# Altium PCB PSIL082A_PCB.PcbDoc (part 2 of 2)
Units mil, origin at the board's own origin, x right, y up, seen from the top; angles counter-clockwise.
Board outline 3500 x 2700 mil, 4 copper layers (Top Layer, Signal Layer 1, Signal Layer 2, Bottom Layer), stack 61.2 mil thick; 62 components, 57 nets, 283 pads, 94 vias.
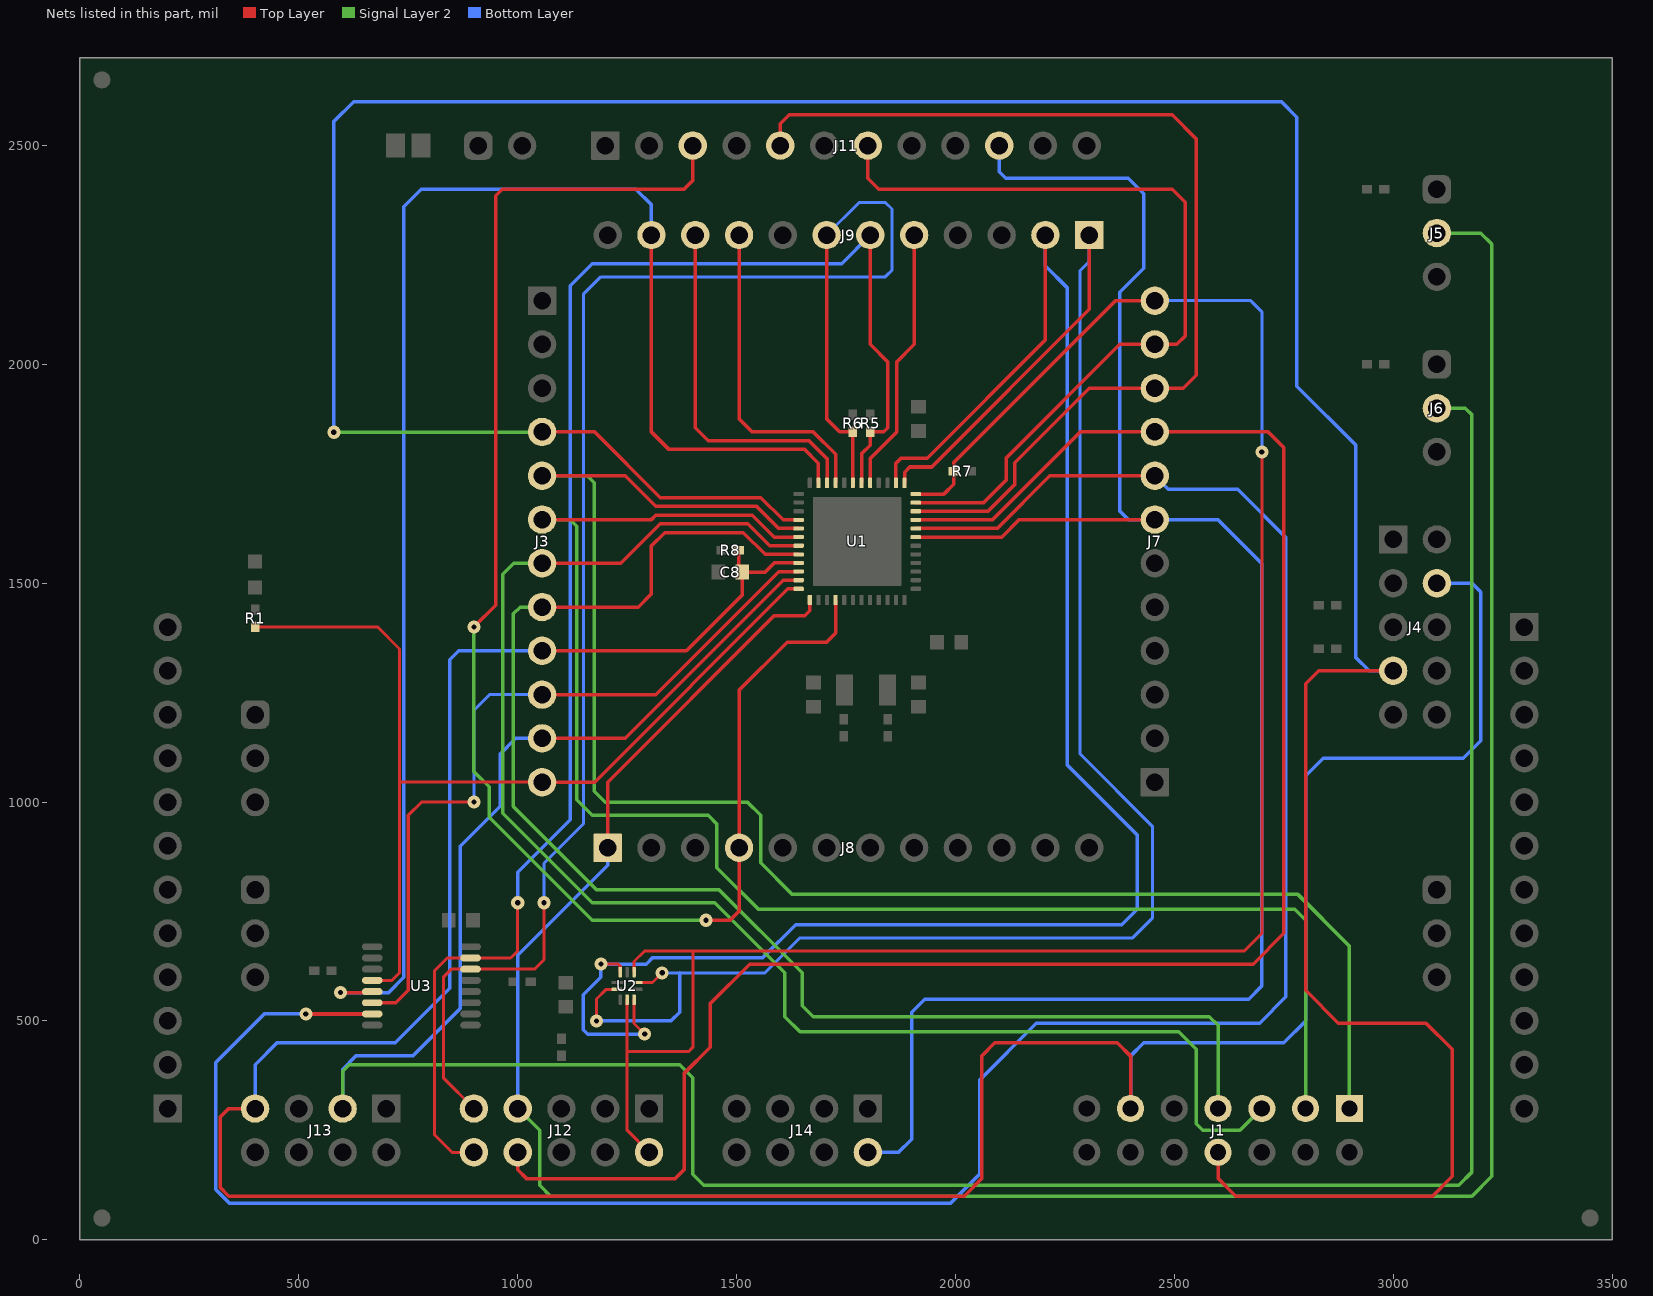
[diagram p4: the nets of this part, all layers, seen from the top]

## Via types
v1: diameter 30, hole 12, Top Layer to Bottom Layer, 73 vias
v2: diameter 19.68, hole 7.87, Top Layer to Bottom Layer, 21 vias

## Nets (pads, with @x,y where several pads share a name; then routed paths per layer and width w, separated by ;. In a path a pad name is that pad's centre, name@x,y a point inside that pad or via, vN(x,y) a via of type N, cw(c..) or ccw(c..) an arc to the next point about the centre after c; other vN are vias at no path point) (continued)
"P1.6 PG2": J7.7 J11.10 J14.2 U1.19 | length 4288.3
  Top Layer w8: U1.19@1909.45,1605.43 2105.43,1605.43 2145.59,1645.59 J7.7@2455.59,1645.59
  Bottom Layer w8: J14.2@1800,200 1870,200 1900,230 1900,520 1930,550 2670,550 2700,580 2700,1545 2599.41,1645.59 J7.7@2455.59,1645.59 2394.41,1645.59 2375,1665 2375,2165.01 2430,2220.01 2430,2390 2395,2425 2115,2425 2100,2440 J11.10@2100,2500
"P1.7 DIS PORTS": J7.8 U1.20 U3.7 | length 5476.9
  Top Layer w8: U1.20@1909.45,1625.12 2095.12,1625.12 2215.59,1745.59 J7.8@2455.59,1745.59
  Top Layer w10: v1(516.02,516.02) U3.7@667.8,516.02
  Bottom Layer w8: v1(516.02,516.02) 421.02,516.02 310,405 310,115 341.87,83.13 1988.13,83.13 2055,150 2055,365 2185,495 2695,495 2755,555 2755,1604.65 2644.65,1715 2486.18,1715 J7.8@2455.59,1745.59
"P2.7 SPI CLK USCI_A0": J7.9 J12.8 U1.21 | length 4266.2
  Top Layer w8: J12.8@1000,200 1000,160 1020,140 1360,140 1380,160 1380,380 1440,440 1440,540 1530,630 2680,630 2750,700 2750,1810 2714.41,1845.59 2285.59,1845.59 2084.8,1644.8 U1.21@1909.45,1644.8
"P3.0 I2C SDA USCI_B0": J7.10 J11.5 U1.22 | length 2369.5
  Top Layer w8: J11.5@1600,2500 1600,2550 1620,2570 2495,2570 2550,2515 2550,1975 2520.59,1945.59 2305.59,1945.59 2135.59,1775.59 2135.59,1725.59 2074.49,1664.49 U1.22@1909.45,1664.49
"P3.1 I2C SCL USCI_B0": J7.11 J11.7 U1.23 | length 1930.4
  Top Layer w8: J11.7@1800,2500 1800,2425 1825,2400 2495,2400 2525,2370 2525,2065 2505.59,2045.59 2375.59,2045.59 2115.59,1785.59 2115.59,1735.59 2064.17,1684.17 U1.23@1909.45,1684.17
"P3.2 SPI SLAVE TX EN USCI_A0": J7.12 J12.2 R7.1 U1.24 U2.4 U2.8 | length 4661.9
  Top Layer w7: U2.4@1250,548.5 1250,430 ; U2.8@1265.75,611.5 1265.75,635.75 1290,660 1400,660 ; J12.2@1300,200 1250,250 1250,430 ; v1(2700,1800) 2700,700 2660,660 1400,660 ; 1250,430 1390,430 1400,440 1400,660
  Top Layer w8: U1.24@1909.45,1703.86 1973.86,1703.86 1995.91,1725.91 1995.91,1775.91 2365.59,2145.59 J7.12@2455.59,2145.59
  Bottom Layer w7: J7.12@2455.59,2145.59 2674.41,2145.59 2700,2120 v1(2700,1800)
"P3.3 UART TX USCI_A0/SPI SIMO": J9.1 U1.25 U2.2 U2.7 | length 4038.4
  Top Layer w7: v1(1180,500) 1180,550 1202.13,572.13 U2.2@1226.38,572.13 ; U2.7@1273.62,587.87 1307.87,587.87 v1(1330,610)
  Top Layer w8: U1.25@1883.86,1729.45 1883.86,1753.86 1895.59,1765.59 1945.59,1765.59 2305.59,2125.59 J9.1@2305.59,2295.59
  Bottom Layer w7: v1(1330,610) 1565,610 1645,690 2405,690 2450,735 2450,945 2285,1110 2285,2214.41 2305.59,2235 J9.1@2305.59,2295.59
  Bottom Layer w8: v1(1180,500) 1350,500 1370,520 1370,609.65
"P3.4 UART RX USCI_A0/SPI SOMI": J9.2 U1.26 U2.5 U2.10 | length 4106.3
  Top Layer w7: v1(1190,630) 1230,630 1234.25,625.75 U2.10@1234.25,611.5 ; U2.5@1265.75,548.5 1265.75,494.25 v1(1290,470)
  Top Layer w8: U1.26@1864.17,1729.45 1864.17,1774.17 1875.59,1785.59 1935.59,1785.59 2205.59,2055.59 J9.2@2205.59,2295.59
  Bottom Layer w8: v1(1290,470) 1160,470 1150,480 1150,560 1190,600 v1(1190,630) 1293.84,630 1308.84,645 1560,645 1635,720 2380,720 2415,755 2415,925 2255,1085 2255,2175.59 2205.59,2225 J9.2@2205.59,2295.59
"P4.0 SPI CLK USCI_A1": J9.5 U1.29 | length 607.8
  Top Layer w8: U1.29@1805.12,1729.45 1805.12,1785.12 1865.59,1845.59 1865.59,2005.59 1905.59,2045.59 J9.5@1905.59,2295.59
"P4.1 I2C SDA USCI_B1": J9.6 J12.10 R5.1 U1.30 U3.15 | length 3618.8
  Top Layer w7: J12.10@900,200 850,200 810,240 810,615 838.98,643.98 U3.15@892.2,643.98 983.98,643.98 1000,660 v1(1000,770)
  Top Layer w8: U1.30@1785.43,1729.45 1785.43,1795.43 1805.59,1815.59 R5.1@1805.59,1845.91 1835.91,1845.91 1845.59,1855.59 1845.59,2005.59 1805.59,2045.59 J9.6@1805.59,2295.59
  Bottom Layer w8: v1(1000,770) 1000,840 1120,960 1120,2180 1170,2230 1740,2230 J9.6@1805.59,2295.59
"P4.2 I2C SCL USCI_B1": J9.7 J12.9 R6.1 U1.31 U3.14 | length 3795.7
  Top Layer w7: J12.9@900,300 830,370 830,600 848.39,618.39 U3.14@892.2,618.39 1038.39,618.39 1060,640 v1(1060,770)
  Top Layer w8: J9.7@1705.59,2295.59 1705.59,1875.59 1735.28,1845.91 R6.1@1765.59,1845.91 ; U1.31@1765.75,1729.45 R6.1@1765.75,1845.75
  Bottom Layer w7: v1(1060,770) 1060,860 1150,950 1150,2160 1190,2200 1840,2200 1855,2215 1855,2355 1840,2370 1780,2370 J9.7@1705.59,2295.59
"P4.4 SPI SIMO/UART TX USCI_A1": J9.9 U1.33 | length 739.6
  Top Layer w8: J9.9@1505.59,2295.59 1505.59,1875.59 1535.59,1845.59 1675.59,1845.59 1726.38,1794.8 U1.33@1726.38,1729.45
"P4.5 SPI SOMI/UART RX USCI_A1": J9.10 U1.34 | length 825.6
  Top Layer w8: J9.10@1405.59,2295.59 1405.59,1855.59 1435.59,1825.59 1665.59,1825.59 1706.69,1784.49 U1.34@1706.69,1729.45
"P4.6 RESERVED": J9.11 U1.35 U3.5 | length 3564.6
  Top Layer w8: v1(595,565) 665.59,565 U3.5@667.8,567.2 ; J9.11@1305.59,2295.59 1305.59,1845.59 1345.59,1805.59 1655.59,1805.59 1687.01,1774.17 U1.35@1687.01,1729.45
  Bottom Layer w8: v1(595,565) 705,565 740,600 740,2360 780,2400 1270,2400 1305.59,2364.41 J9.11@1305.59,2295.59
"P5.0 RESET": J8.4 J11.3 U1.4 | length 3531.5
  Top Layer w8: v1(900,1400) 950,1450 950,2385 965,2400 1380,2400 1400,2420 J11.3@1400,2500 ; v1(1430,730) 1485,730 1505.59,750.59 J8.4@1505.59,895.59 1505.59,1255.59 1615.59,1365.59 1705.59,1365.59 1726.38,1386.38 U1.4@1726.38,1461.73
  Signal Layer 2 w8: v1(900,1400) 900,1070 935,1035 935,965 1170,730 v1(1430,730)
"P6.0 INT to host": J3.10 U1.46 U3.6 | length 1739.3
  Top Layer w7: U3.6@667.8,541.61 721.61,541.61 750,570 750,970 780,1000 v1(900,1000)
  Top Layer w8: J3.10@1055.59,1245.59 1315.59,1245.59 1596.69,1526.69 U1.46@1641.73,1526.69
  Bottom Layer w7: v1(900,1000) 900,1210 935.59,1245.59 J3.10@1055.59,1245.59
"P6.1 I2C or UART/SPI": J3.11 J6.2 J13.3 U1.47 | length 6624.1
  Top Layer w8: J3.11@1055.59,1145.59 1245.59,1145.59 1607.01,1507.01 U1.47@1641.73,1507.01
  Signal Layer 2 w8: J13.3@600,300 600,385 615,400 1370,400 1400,370 1400,150 1425,125 3150,125 3180,155 3180,1885 3165,1900 J6.2@3100,1900
  Bottom Layer w8: J13.3@600,300 600,390 630,420 760,420 868.58,528.58 868.58,899.29 960,990.71 960,1110 995.59,1145.59 J3.11@1055.59,1145.59
"P6.2 GUARDBAND": J3.12 R1.1 U1.48 U3.4 | length 2254.9
  Top Layer w7: R1.1@400,1400.32 679.68,1400.32 730,1350 730,1045.59 ; U3.4@667.8,592.8 712.8,592.8 730,610 730,1045.59 ; J3.12@1055.59,1045.59 730,1045.59
  Top Layer w8: J3.12@1055.59,1045.59 1175.59,1045.59 1617.32,1487.32 U1.48@1641.73,1487.32
"P6.3 BSL SEL": J5.2 J8.1 J12.7 U1.1 | length 6144.2
  Top Layer w8: J8.1@1205.59,895.59 1205.59,1045.59 1585.59,1425.59 1655.59,1425.59 1667.32,1437.32 U1.1@1667.32,1461.73
  Signal Layer 2 w8: J12.7@1000,300 1050,250 1050,125 1075,100 3180,100 3225,145 3225,2275 3200,2300 J5.2@3100,2300
  Bottom Layer w8: J12.7@1000,300 1000,650 1205.59,855.59 J8.1@1205.59,895.59
RSTDVCC/SBWTDIO: C8.1 J1.11 J3.9 J4.4 J13.7 R8.2 U1.45 | length 7112.4
  Top Layer w8: J13.7@400,300 340,300 320,280 320,120 340,100 2020,100 2060,140 2060,420 2090,450 2370,450 2400,420 J1.11@2400,300 ; J3.9@1055.59,1345.59 1385.59,1345.59 1513.15,1473.15 C8.1@1513.15,1525.59 ; R8.2@1505.28,1575.59 1505.28,1533.46 C8.1@1513.15,1525.59 ; U1.45@1641.73,1546.38 1586.38,1546.38 1565.59,1525.59 C8.1@1513.15,1525.59
  Bottom Layer w8: J13.7@400,300 400,400 450,450 720,450 845,575 845,1325 865.59,1345.59 J3.9@1055.59,1345.59 ; J1.11@2400,300 2400,420 2430,450 2750,450 2800,500 2800,1060 2840,1100 3160,1100 3200,1140 3200,1480 3180,1500 J4.4@3100,1500
TCK: J1.7 J3.8 U1.44 | length 3304.6
  Top Layer w8: J3.8@1055.59,1445.59 1275.59,1445.59 1305.59,1475.59 1305.59,1585.59 1335.59,1615.59 1515.59,1615.59 1565.12,1566.06 U1.44@1641.73,1566.06
  Signal Layer 2 w8: J3.8@1055.59,1445.59 1005.59,1445.59 990,1430 990,990 1180,800 1460,800 1650,610 1650,535 1675,510 2580,510 2600,490 J1.7@2600,300
TDI/TCLK: J1.3 J3.6 U1.42 | length 3589.4
  Top Layer w8: J3.6@1055.59,1645.59 1305.59,1645.59 1315.59,1655.59 1535.59,1655.59 1585.75,1605.43 U1.42@1641.73,1605.43
  Signal Layer 2 w8: J3.6@1055.59,1645.59 1119.41,1645.59 1135,1630 1135,1005 1170,970 1435,970 1455,950 1455,850 1550,755 2775,755 2800,730 J1.3@2800,300
TDO: J1.1 J3.5 U1.41 | length 3773.4
  Top Layer w8: J3.5@1055.59,1745.59 1245.59,1745.59 1315.59,1675.59 1545.59,1675.59 1596.06,1625.12 U1.41@1641.73,1625.12
  Signal Layer 2 w8: J3.5@1055.59,1745.59 1159.41,1745.59 1175,1730 1175,1025 1200,1000 1525,1000 1555,970 1555,861.37 1626.37,790 2781.37,790 2900,671.37 J1.1@2900,300
TEST/SBWTCK: J1.8 J3.4 J4.7 U1.40 | length 7699.3
  Top Layer w8: J3.4@1055.59,1845.59 1175.59,1845.59 1325.59,1695.59 1555.59,1695.59 1606.38,1644.8 U1.40@1641.73,1644.8 ; J1.8@2600,200 2600,140 2640,100 3090,100 3135,145 3135,435 3075,495 2875,495 2800,570 2800,1270 2830,1300 J4.7@3000,1300
  Signal Layer 2 w8: v1(580,1845) J3.4@1055,1845
  Bottom Layer w8: v1(580,1845) 580,2555 625,2600 2745,2600 2780,2565 2780,1950 2915,1815 2915,1330 2945,1300 J4.7@3000,1300
TMS: J1.5 J3.7 U1.43 | length 3503.9
  Top Layer w8: J3.7@1055.59,1545.59 1235.59,1545.59 1325.59,1635.59 1525.59,1635.59 1575.43,1585.75 U1.43@1641.73,1585.75
  Signal Layer 2 w8: J3.7@1055.59,1545.59 990.59,1545.59 965.59,1520.59 965.59,974.41 1170,770 1450,770 1610,610 1610,510 1645,475 2510,475 2550,435 2550,265 2565,250 2650,250 J1.5@2700,300
pads on no net: FID1.1 FID2.1 FID3.1 J1.6 J1.10 J1.12 J1.13 J1.14 J3.2 J3.3 J4.2 J4.9 J4.10 J8.7 J8.8 J8.12 J11.11 J13.1 J13.2 J13.5 J13.6 J14.1 J14.3 J14.4 J14.5 J14.6 J14.7 J14.8 J17.2 J17.3 J17.4 J17.5 J17.7 J17.8 J17.9 J17.10 J17.11 J18.2 J18.3 J18.4 J18.5 J18.7 J18.8 J18.9 J18.10 J18.11 LBL1.0 SH-J1.0 SH-J2.0 SH-J3.0 SH-J4.0 SH-J5.0 U1.38 U1.39 U3.9 U3.10 U3.11 U3.12

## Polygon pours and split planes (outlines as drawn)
GND_ISO on Signal Layer 1 "SIGNAL_LAYER_1_GND_ISO_P000" (solid, remove dead copper, pour order 0): 50,2650 3450,2650 3450,50 50,50
DVCC on Signal Layer 2 "SIGNAL_LAYER_2_DVCC_P002" (solid, remove dead copper, pour order 2): 50,2650 50,50 3450,50 3450,2650
GND_ISO on Top Layer "TOP_LAYER_GND_ISO_P004" (solid, remove dead copper, pour order 4): 50,2650 3450,2650 3450,50 50,50
GND_ISO on Bottom Layer "BOTTOM_LAYER_GND_ISO_P006" (solid, remove dead copper, pour order 6): 3450,2650 3450,50 50,50 50,2650

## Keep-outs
Keep-Out Layer:
  lines w10: -5,0 ccw(c0,0) 0,-5 ; -5,0 ccw(c0,0) 0,-5 ; -5,0 -5,2700 ; -5,2700 cw(c0,2700) 0,2705 ; -5,2700 cw(c0,2700) 0,2705 ; 0,-5 3500,-5 ; 0,2705 3500,2705 ; 3500,-5 ccw(c3500,0) 3505,0 ; 3500,-5 ccw(c3500,0) 3505,0 ; 3500,2705 cw(c3500,2700) 3505,2700 ; 3500,2705 cw(c3500,2700) 3505,2700 ; 3505,0 3505,2700
  text ".Layer_Name" at 577,-858.49 h60

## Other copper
Top Layer:
  text ".Layer_Name" at 567,-858.49 h60
Signal Layer 1:
  text ".Layer_Name" at 577,-858.49 h60
Signal Layer 2:
  text ".Layer_Name" at 572,-863.49 h60
Bottom Layer:
  text ".Layer_Name" at 577,-858.49 h60

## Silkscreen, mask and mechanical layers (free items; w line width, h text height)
Top Overlay:
  lines w8: 1045,350 1045,390 1150,390 1150,350
  text "DVCC/3.3V_ISO" at 735,2585 h72.83
  text "'.PRJ_Number'.PCB_Rev" at 160,2460 h108.27
  text "HIGH" at 3190,2380 h72.83
  text "PIN 25" at 2290,2365 h70
  text "PIN 36" at 1035,2360 h70
  text "Reserved" at 3187.88,2270.75 h72.83
  text "LOW" at 3190,2170 h72.83
  text "PIN 37" at 780,2125 h70
  text "PIN 24" at 2535,2120 h70
  text "I2C" at 3170,1985 h72.83
  text "UART/SPI" at 3165,1775 h72.83
  text "BSL" at 3195,1490 h72.83
  text "PIN 48" at 795,1030 h70
  text "PIN 13" at 2535,1015 h70
  text "PIN 1" at 1085,785 h70
  text "INT" at 2829.25,784.63 h72.83
  text "PIN 12" at 2300,775 h70
  text "DVCC" at 2829.25,684.99 h72.83
  text "EXT" at 2829.25,582.12 h72.83
  text "JTAG" at 2510,460 h72.83
  text "(29)" at 315,390 h72.83
  text "(1)" at 1770,390 h72.83
  text "9" at 850,360 h72.83
  text "1" at 1330.53,357.71 h72.83
  text "2" at 1315,95 h72.83
  text "10" at 845,90 h72.83
  text "USB2ANY" at 950,80 h72.83
  text "(2)" at 1770,70 h72.83
  text "(30)" at 310,60 h72.83
  text ".Layer_Name" at 577,-858.49 h60
Bottom Overlay:
  text ".Layer_Name" at 577,-858.49 h60
Top Paste:
  text ".Layer_Name" at 577,-858.49 h60
Bottom Paste:
  text ".Layer_Name" at 577,-858.49 h60
Top Solder:
  text ".Layer_Name" at 577,-858.49 h60
  text ".Layer_Name" at 577,-858.49 h60
Bottom Solder:
  text ".Layer_Name" at 577,-858.49 h60
Drill Guide:
  text ".Layer_Name" at 577,-858.49 h60
M1 Board Outline:
  the board outline again, w10
  text ".Layer_Name" at 577,-858.49 h60
M2 Board Dimensions:
  rectangle: 125,-400 500,-275
  rectangle: 0,-275 125,-150
  lines w7: 0,-275 1000,-275 ; 125,-400 125,-150 ; 250,-400 250,-150 ; 500,-400 500,-150 ; 750,-400 750,-150 ; 0,-400 0,-150 1000,-150 1000,-400 0,-400
  text ".Layer_Name" at 577,-858.49 h60
M3 3D STEP Top:
  text ".Layer_Name" at 577,-858.49 h60
M4 3D STEP Bottom:
  text ".Layer_Name" at 577,-858.49 h60
M5 Assembly Top:
  lines w10: -292,-930.17 6308,-930.17 ; -292,-726.83 6310,-726.83 ; -292,-523.5 -292,-1133.5 3713,-1133.5 6310,-1133.5 6310,-523.5 -291.5,-523.5 -291.5,-1133.5 1284,-1133.5 ; 2173,-1133.5 2173,-523.5 ; 3440,-726.83 3440,-523.5 ; 4280,-726.83 4280,-523.5 ; 4902,-1140 4902,-937.17
  text "COMPONENTS MARKED 'DNP' SHOULD NOT BE POPULATED." at 1153.5,-318.5 h60
  text "ASSEMBLY VARIANT:" at 1153,-434 h60
  text ".VariantName" at 2189,-434 h60
  text "PCB VIEWED FROM TOP SIDE" at -228.5,-655.67 h60
  text "BOARD #:" at 2248,-655.67 h60
  text ".PRJ_Number" at 2793.5,-655.67 h60
  text "REV:" at 3638,-655.67 h60
  text ".PCB_Rev" at 3929.5,-655.67 h60
  text "SVN REV:" at 4476,-655.67 h60
  text ".VersionControl_RevNumber" at 4982,-655.67 h60
  text "TID #:" at 2248,-859 h60
  text ".TID" at 2793.5,-859 h60
  text "PLOT NAME =" at -228.5,-1064.34 h60
  text ".plot_File_Name" at 577,-1064.34 h60
  text "GENERATED    :" at 2250,-1064.34 h60
  text ".Print_Date" at 3119.5,-1064.34 h60
  text ".Print_Time" at 3848.5,-1064.34 h60
  text "TEXAS INSTRUMENTS" at 5113,-1064.34 h60
M6 Assembly Bottom:
  lines w10: -292.5,-727.33 6309.5,-727.33 ; -290.5,-930.67 6309.5,-930.67 ; 1115.5,-1140.5 1115.5,-937.67 ; 1737.5,-727.33 1737.5,-524 ; 2577.5,-727.33 2577.5,-524 ; 3844.5,-1134 3844.5,-524 ; 4733.5,-1134 6309,-1134 6309,-524 -292.5,-524 -292.5,-1134 2304.5,-1134 6309.5,-1134 6309.5,-524
  text "COMPONENTS MARKED 'DNP' SHOULD NOT BE POPULATED." at 6102,-318 h60
  text ".VariantName" at 5058,-434 h60
  text "ASSEMBLY VARIANT:" at 6097,-434 h60
  text ".VersionControl_RevNumber" at 1035.5,-656.17 h60
  text "SVN REV:" at 1541.5,-656.17 h60
  text ".PCB_Rev" at 2088,-656.17 h60
  text "REV:" at 2379.5,-656.17 h60
  text ".PRJ_Number" at 3224,-656.17 h60
  text "BOARD #:" at 3769.5,-656.17 h60
  text "PCB VIEWED FROM BOTTOM SIDE" at 6246,-656.17 h60
  text ".TID" at 3224,-859.5 h60
  text "TID #:" at 3769.5,-859.5 h60
  text "TEXAS INSTRUMENTS" at 904.5,-1064.84 h60
  text ".Print_Time" at 2169,-1064.84 h60
  text ".Print_Date" at 2898,-1064.84 h60
  text "GENERATED    :" at 3767.5,-1064.84 h60
  text ".plot_File_Name" at 5440.5,-1064.84 h60
  text "PLOT NAME =" at 6246,-1064.84 h60
M9 Title Sheet:
  drawing of 57 lines, arcs and shapes, not listed
  text "1" at 739.84,8036.5 h70
  text "2" at 3235.5,8036.5 h70
  text "3" at 5724.84,8036.5 h70
  text "4" at 8231.51,8036.5 h70
  text "5" at 10730.5,8036.5 h70
  text "6" at 13235.5,8036.5 h70
  text "A" at -416.5,6893.5 h70
  text "A" at 14383.5,6893.5 h70
  text "B" at -416.5,4513.5 h70
  text "B" at 14383.5,4513.5 h70
  text "C" at -416.5,2138.5 h70
  text "C" at 14383.5,2138.5 h70
  text "PROJECT TITLE:" at 11343.5,277.5 h45
  text ".PRJ_Title" at 11393.5,144.17 h70
  text "DESIGNED FOR:" at 11343.5,-23.5 h45
  text ".PRJ_Customer" at 11393.5,-163.5 h70
  text "D" at -416.5,-231.5 h70
  text "D" at 14383.5,-231.5 h70
  text "FILE NAME:" at 11343.5,-323.5 h45
  text ".PCB_File_Name_No_Path" at 11393.5,-443.5 h70
  text "Texas Instruments (TI) and/or its licensors do not warrant the accuracy or completeness of this specification" at 6374,-605.34 h45
  text "ENGINEER:" at 11343.5,-613.5 h45
  text "LAYOUT BY:" at 12848.5,-613.5 h45
  text "or any information contained therein. TI and/or its licensors do not warrant that this design will meet" at 6329.01,-718 h45
  text ".PRJ_Engineer" at 11393.5,-768.49 h70
  text ".PCB_Layout" at 12899,-768.49 h70
  text "the specifications, will be suitable for your application or fit for any particular purpose, or will operate in" at 6329.01,-830.67 h45
  text ".Layer_Name" at 577,-858.49 h60
  text "ALTIUM DESIGNER VERSION:" at 12848.5,-923.5 h45
  text "an implementation. TI and/or its licensors do not warrant that the design is production worthy. You should" at 6329.01,-943.33 h45
  text "completely validate and test your design implementation to confirm the system functionality for your application." at 6374,-1056 h45
  text ".print_Scale" at 11393.5,-1056.83 h70
  text ".Application_BuildNumber" at 12899,-1056.83 h70
  text "1" at 739.84,-1263.5 h70
  text "2" at 3235.5,-1263.5 h70
  text "3" at 5724.84,-1263.5 h70
  text "4" at 8231.51,-1263.5 h70
  text "5" at 10730.5,-1263.5 h70
  text "6" at 13235.5,-1263.5 h70
M10 Fab Notes:
  drawing of 189 lines, arcs and shapes, not listed
  text "DESIGN INFORMATION" at 12382.02,6356.17 h60
  text "MIN. TRACK WIDTH:" at 11737.46,6224.05 h60
  text "7" at 12833.7,6224.05 h60
  text "MIL" at 12988.46,6224.05 h60
  text "MIN. CLEARANCE:" at 11737.46,6099.92 h60
  text "0.2" at 12773.7,6099.93 h60
  text "mm" at 12988.46,6099.92 h60
  text "MIN. VIA PAD SIZE:" at 11737.46,5975.8 h60
  text "24" at 12803.71,5975.8 h60
  text "MIL" at 12988.46,5975.8 h60
  text "0.05mm (2MIL)" at 12432.46,5845.9 h60
  text "MINIMUM ANNULAR RING" at 11408.23,5837.67 h60
  text "EXTERNAL" at 13140.46,5837.67 h60
  text "PER" at 11608.23,5727.55 h60
  text "IPC-D-275 CLASS 2 LEVEL C" at 11828.23,5727.54 h60
  text "MIL, HOLES" at 13316.46,5627.07 h60
  text "+/-" at 12924,5618.48 h60
  text "+/-" at 13778,5618.48 h60
  text "REGISTRATION TOLERANCES:" at 11408.23,5617.42 h60
  text "METAL" at 12608,5617.42 h60
  text "5" at 13184.2,5617.42 h60
  text "3" at 14017.2,5617.42 h60
  text "MIL" at 14133.46,5617.42 h60
  text "HOLE SIZE TOLERANCE (UNLESS OTHERWISE SPECIFIED):" at 11408.23,5519.1 h60
  text "+/-" at 13778,5516.23 h60
  text "3" at 14017.2,5515.17 h60
  text "MIL" at 14133.46,5515.17 h60
  text "MATERIAL:" at 11333.46,5377.52 h60
  text "FR-4 High Tg" at 12319.9,5249 h60
  text "X" at 12175.46,5241.01 h60
  text "FR-408" at 11754.46,5236.49 h60
  text "OTHER" at 13242.46,5236.49 h60
  text "62 MIL (1.6mm) +/-10%" at 12074.56,5093.46 h60
  text "X" at 11954.46,5091.01 h60
  text "THICKNESS:" at 11408.23,5085.24 h60
  text "OTHER" at 13359.46,5085.24 h60
  text "TOLERANCE:" at 11408.23,4946.92 h60
  text "X" at 12256.46,4946.92 h60
  text "ANSI IPC-6012 TYPE 3 CLASS 2" at 12434.48,4946.92 h60
  text "OTHER +/-" at 12434.46,4802.73 h60
  text "BOW & TWIST:" at 11408.23,4657.54 h60
  text "X" at 12256.46,4657.54 h60
  text "ANSI IPC-6012 TYPE 3 CLASS 2" at 12434.48,4657.54 h60
  text "OTHER +/-" at 12434.46,4510.85 h60
  text "DRILLING:" at 11333.46,4380.23 h60
  text "NC_DRILL FILES" at 13094.46,4275.04 h60
  text "REFERENCE:" at 11408.23,4271.1 h60
  text "X" at 12065.46,4271.01 h60
  text "AS SHOWN" at 12243.46,4271.1 h60
  text "X" at 12966.46,4271.1 h60
  text "OTHER" at 13392.46,4128.85 h60
  text "PTH COPPER THICKNESS:" at 11407.91,4125.32 h60
  text "X" at 12547.14,4125.32 h60
  text "20-30 um" at 12675.14,4125.32 h60
  text "BOARD FINISH:" at 11333.46,3977.73 h60
  text "SILKSCREEN:" at 11488.68,3867.6 h60
  text "X" at 12446.46,3867.6 h60
  text "TOP" at 12563.46,3867.6 h60
  text "X" at 12956.46,3867.6 h60
  text "BOTTOM" at 13074.46,3867.6 h60
  text "SILKSCREEN COLOR:" at 11488.68,3712.41 h60
  text "X" at 12445.46,3712.41 h60
  text "WHITE" at 12563.46,3712.41 h60
  text "OTHER" at 13074.46,3712.41 h60
  text "X" at 12576.46,3568.96 h60
  text "GREEN" at 12694.46,3568.96 h60
  text "OTHER" at 13312.46,3568.96 h60
  text "SOLDER RESIST COLOR:" at 11488.68,3562.1 h60
  text "X" at 12576.46,3414.71 h60
  text "MATTE" at 12694.46,3414.71 h60
  text "SEMI-GLOSS" at 13312,3414.07 h60
  text "IMMERSION GOLD (ENIG)" at 12394.46,3241.94 h60
  text "ENEPIG" at 13732,3234.72 h60
  text "SURFACE FINISH:" at 11333.46,3233.72 h60
  text "X" at 12216.46,3233.72 h60
  text "IMM. TIN/SILVER OR EQUIV" at 11663,3096.4 h60
  text "OTHER" at 13094.46,3092.47 h60
  text "ARRAY/PANEL:" at 11333.46,2937.09 h60
  text "X" at 12220,2935 h60
  text "CUT AND TRIM PER M1 BOARD OUTLINE" at 12394.46,2928.87 h60
  text "N.C. ROUTE" at 12394.46,2792.9 h60
  text "V. SCORE" at 13260.46,2792.9 h60
  text "CERTIFICATION:" at 11333.46,2663.77 h60
  text "MATERIALS AND WORKMANSHIP FOR ALL PCBS" at 12058.46,2663.77 h60
  text "TO MEET OR EXCEED THE REQUIREMENTS OF:" at 12058.46,2569.71 h60
  text "X" at 11695.97,2441.08 h60
  text "ANSI IPC-A-600F CLASS ->" at 11823.96,2441.08 h60
  text "X" at 13471.97,2441.08 h60
  text "2" at 13581.96,2441.08 h60
  text "1" at 13266.96,2439.58 h60
  text "3" at 13935.96,2439.58 h60
  text "X" at 12507.97,2293.39 h60
  text "RoHS" at 12635.96,2293.39 h60
  text "OTHER" at 13280.36,2293.39 h60
  text "PER ORDER" at 13677.42,2293.39 h60
  text "ALL BOARDS MUST MEET OR EXCEED UL94-V0 REQUIREMENTS." at 11361,2139.57 h60
  text "PCB MUST BEAR THE UL94V-0 UL REGISTERED MATERIAL ID NUMBER" at 11361,2023.5 h60
  text "ADDITIONAL REQUIREMENTS:" at 11333.46,1854.08 h60
  text "MICROSECTION:" at 11408.23,1746.95 h60
  text "YES" at 12313.96,1746.95 h60
  text "REQUIRED" at 13175.46,1602.62 h60
  text "BARE BOARD ELEC. TEST:" at 11408.23,1599.76 h60
  text "NONE" at 12713.96,1599.76 h60
  text "X" at 13057.46,1599.76 h60
  text "PER ORDER" at 13767.46,1599.76 h60
  text "XX MIL VIAS REQUIRE NON-CONDUCTIVE FILL AND PLANARIZE" at 11576.38,1394.82 h59
  text "XX MIL VIAS REQUIRE CONDUCTIVE FILL AND PLANARIZE" at 11584.38,1290.84 h60
  text "OUTER XX MIL TRACES REQUIRE 50 OHM SINGLE-ENDED IMPEDANCE" at 11583.39,1127.46 h58
  text "LAYER 2 & 3 (INNER LAYERS) XX MIL WIDE, XX MIL SPACE / TRACES REQUIRE 100 OHM DIFFERENTIAL IMPEDANCE" at 11575.39,891.74 h60
  text ".Layer_Name" at 577,-858.49 h60
M11 Gerber Information:
  lines w10: -292,-930.17 6308,-930.17 ; -292,-726.83 6310,-726.83 ; -292,-523.5 -292,-1133.5 3713,-1133.5 6310,-1133.5 6310,-523.5 -291.5,-523.5 -291.5,-1133.5 1284,-1133.5 ; 2173,-1133.5 2173,-523.5 ; 3440,-726.83 3440,-523.5 ; 4280,-726.83 4280,-523.5 ; 4902,-1140 4902,-937.17
  text "ALL ARTWORK VIEWED FROM TOP SIDE" at -228.5,-655.67 h60
  text "BOARD #:" at 2248,-655.67 h60
  text ".PRJ_Number" at 2793.5,-655.67 h60
  text "REV:" at 3638,-655.67 h60
  text ".PCB_Rev" at 3929.5,-655.67 h60
  text "SVN REV:" at 4476,-655.67 h60
  text ".VersionControl_RevNumber" at 4982,-655.67 h60
  text "LAYER NAME =" at -228.5,-858.49 h60
  text "TID #:" at 2248,-859 h60
  text ".TID" at 2793.5,-859 h60
  text "PLOT NAME =" at -228.5,-1064.34 h60
  text ".plot_File_Name" at 577,-1064.34 h60
  text "GENERATED    :" at 2250,-1064.34 h60
  text ".Print_Date" at 3119.5,-1064.34 h60
  text ".Print_Time" at 3848.5,-1064.34 h60
  text "TEXAS INSTRUMENTS" at 5113,-1064.34 h60
M12 Stackup:
  drawing of 295 lines, arcs and shapes, not listed
  text "Layer" at 9760.88,7844.68 h60
  text "Name" at 10170.8,7844.68 h60
  text "Material" at 11110.54,7844.68 h60
  text "Thickness" at 11970.3,7844.68 h60
  text "Constant" at 12620.14,7844.68 h60
  text "Board Layer Stack" at 13190,7844.68 h60
  text "1" at 9760.88,7724.68 h60
  text "Top Overlay" at 10170.8,7724.68 h60
  text "2" at 9760.88,7604.68 h60
  text "Top Solder" at 10170.8,7604.68 h60
  text "Solder Resist" at 11110.54,7604.68 h60
  text "0.40mil" at 11970.3,7604.68 h60
  text "3.5" at 12620.14,7604.68 h60
  text "3" at 9760.88,7484.68 h60
  text "Top Layer" at 10170.8,7484.68 h60
  text "Copper" at 11110.54,7484.68 h60
  text "1.40mil" at 11970.3,7484.68 h60
  text "4" at 9760.88,7364.68 h60
  text "Dielectric 2" at 10170.8,7364.68 h60
  text "FR-4" at 11110.54,7364.68 h60
  text "20.00mil" at 11970.3,7364.68 h60
  text "4.2" at 12620.14,7364.68 h60
  text "5" at 9760.88,7244.68 h60
  text "Signal Layer 1" at 10170.8,7244.68 h60
  text "Copper" at 11110.54,7244.68 h60
  text "1.40mil" at 11970.3,7244.68 h60
  text "6" at 9760.88,7124.68 h60
  text "Dielectric1" at 10170.8,7124.68 h60
  text "FR-4" at 11110.54,7124.68 h60
  text "15.60mil" at 11970.3,7124.68 h60
  text "4.2" at 12620.14,7124.68 h60
  text "7" at 9760.88,7004.68 h60
  text "Signal Layer 2" at 10170.8,7004.68 h60
  text "Copper" at 11110.54,7004.68 h60
  text "1.40mil" at 11970.3,7004.68 h60
  text "8" at 9760.88,6884.68 h60
  text "Dielectric 3" at 10170.8,6884.68 h60
  text "FR-4" at 11110.54,6884.68 h60
  text "20.00mil" at 11970.3,6884.68 h60
  text "4.2" at 12620.14,6884.68 h60
  text "9" at 9760.88,6764.68 h60
  text "Bottom Layer" at 10170.8,6764.68 h60
  text "Copper" at 11110.54,6764.68 h60
  text "1.40mil" at 11970.3,6764.68 h60
  text "10" at 9760.88,6644.68 h60
  text "Bottom Solder" at 10170.8,6644.68 h60
  text "Solder Resist" at 11110.54,6644.68 h60
  text "0.40mil" at 11970.3,6644.68 h60
  text "3.5" at 12620.14,6644.68 h60
  text "11" at 9760.88,6524.68 h60
  text "Bottom Overlay" at 10170.8,6524.68 h60
  text ".Layer_Name" at 577,-858.49 h60
M13 Component Bodies Top:
  text ".Layer_Name" at 577,-858.49 h60
M14 Component Bodies Bottom:
  text ".Layer_Name" at 577,-858.49 h60
M15 Courtyards Top:
  text ".Layer_Name" at 577,-858.49 h60
M16 Courtyards Bottom:
  text ".Layer_Name" at 577,-858.49 h60
Drill Drawing:
  circle w10: c3788.72,456.96 r27.63
  lines w10: 3761.09,180.7 3816.34,180.7 3816.34,235.95 3761.09,235.95 3761.09,180.7 ; 3761.09,360.27 3816.34,360.27 3788.72,305.02 3761.09,360.27 ; 3761.09,567.47 3774.9,567.47 3788.72,553.66 3802.53,567.47 3816.34,567.47 3802.53,581.28 3816.34,595.1 3802.53,595.1 3788.72,608.91 3774.9,595.1 3761.09,595.1 3774.9,581.28 3761.09,567.47
  lines w12: 3711,143.4 6942.49,143.4 ; 3711,640.68 6942.49,640.68 ; 4048.86,19.08 4048.86,765 ; 4380.86,19.08 4380.86,765 ; 5017.43,19.08 5017.43,765 ; 5276.57,19.08 5276.57,765 ; 5651.72,19.08 5651.72,765 ; 6376.05,19.08 6376.05,765 ; 3711,19.08 6942.49,19.08 6942.49,765 3711,765 3711,19.08
  text "Symbol" at 3785.59,677.98 h72
  text "Quantity" at 4086.16,677.98 h72
  text "Finished Hole Size" at 4418.16,677.98 h72
  text "Plated" at 5054.72,677.98 h72
  text "Hole Type" at 5313.86,677.98 h72
  text "Drill Layer Pair" at 5689.02,677.98 h72
  text "Hole Tolerance" at 6413.35,677.98 h72
  text "21" at 4086.16,553.66 h60
  text "7.87mil (0.200mm)" at 4418.16,553.66 h60
  text "PTH" at 5054.72,553.66 h60
  text "Round" at 5313.86,553.66 h60
  text "Top Layer - Bottom Layer" at 5689.02,553.66 h60
  text "73" at 4086.16,429.34 h60
  text "12.00mil (0.305mm)" at 4418.16,429.34 h60
  text "PTH" at 5054.72,429.34 h60
  text "Round" at 5313.86,429.34 h60
  text "Top Layer - Bottom Layer" at 5689.02,429.34 h60
  text "14" at 4086.16,305.02 h60
  text "37.00mil (0.940mm)" at 4418.16,305.02 h60
  text "PTH" at 5054.72,305.02 h60
  text "Round" at 5313.86,305.02 h60
  text "Top Layer - Bottom Layer" at 5689.02,305.02 h60
  text "137" at 4086.16,180.7 h60
  text "40.00mil (1.016mm)" at 4418.16,180.7 h60
  text "PTH" at 5054.72,180.7 h60
  text "Round" at 5313.86,180.7 h60
  text "Top Layer - Bottom Layer" at 5689.02,180.7 h60
  text "245 Total" at 4086.16,56.38 h60
  text ".Layer_Name" at 577,-858.49 h60
M17 Embedded Cavity:
  text ".Layer_Name" at 577,-858.49 h60
M18 Embedded Assembly:
  text ".Layer_Name" at 577,-858.49 h60
M19 Embedded Keepout:
  text ".Layer_Name" at 577,-858.49 h60

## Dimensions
0,0 to 3500,0 on M2 Board Dimensions
0,0 to 0,2700 on M2 Board Dimensions
0,-400 to 1000,-400 on M2 Board Dimensions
